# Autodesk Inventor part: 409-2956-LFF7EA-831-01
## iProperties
Created: 2010-09
Part Number: 409-2956-LFF7EA-831-01
Material: 3/8" OD TUBE - SS
Document SubType Name: Modeling
Designer: S. Boerckel
Engineer: Steve Boerckel
Mass: 61.6007 g
Surface Area: 127.01 cm^2
Volume: 7.62385 cm^3
Density: 8.08 g/cm^3
Description: LOWE PRESSURE GAUGE TUBE
Length: 14.237 in
Author: S. Boerckel
Revision Number: 0
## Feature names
1. Sweep3
